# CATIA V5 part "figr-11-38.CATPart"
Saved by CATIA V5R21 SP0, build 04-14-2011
Part number: Part1
Bounding box of the stored display mesh (mm): x -177 to 59, y -180 to 60, z 0 to 80
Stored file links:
  D:\CATIA V5R21 E-RESOURCES\CATIA-V5R21\catia-v5r21-prt\c11-catia-v5r21-prt\c11-catia-v5r21-figr-11-38.CATPart
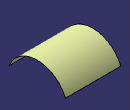
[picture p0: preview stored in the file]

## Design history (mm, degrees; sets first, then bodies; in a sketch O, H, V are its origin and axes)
Set1
  Extrude1: Element1 Sketch1, Lim1 59, Lim2 59, Direction yz-plane
  Scaling1: Reference vertex [face of Extrude1], Ratio 2, ToTransfor Extrude1
Body1 (main body)
  Sketch1 on yz-plane, origin (0, 0, 0), H (0, 1, 0), V (0, 0, 1)
    arc A1 centre (0, -25) radius 65 from (-60, 0) to (60, 0) cw
    point P2 (-60, 0)
    point P3 (60, 0)
    coincidence: P2 H, P3 H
